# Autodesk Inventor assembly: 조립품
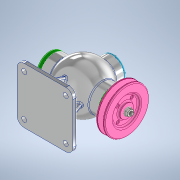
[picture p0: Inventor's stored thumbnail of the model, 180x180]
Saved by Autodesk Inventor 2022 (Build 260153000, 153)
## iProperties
Created: 2024-04
Part Number: 조립품
Document SubType Name: Assembly
Designer: Admin
Author: Admin
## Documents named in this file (16)
- C:\Users\Admin\Desktop\740406V1001\조립품.iam
- C:\Users\Admin\Desktop\740406V1001\본체.ipt
- C:\Users\Admin\Desktop\740406V1001\뒤커버.ipt
- C:\Users\Admin\Desktop\740406V1001\앞커버.ipt
- C:\Users\Admin\Desktop\740406V1001\베어링- 6202.ipt
- KS B 2023 - 6202 - 15 x 35 x 11 - 7.8.ipt
- C:\Users\Admin\Desktop\740406V1001\오일실 15 30 7.ipt
- C:\Users\Admin\Desktop\740406V1001\상부커버.ipt
- C:\Users\Admin\Desktop\740406V1001\칼라.ipt
- C:\Users\Admin\Desktop\740406V1001\편심축.ipt
- C:\Users\Admin\Desktop\740406V1001\키 4 x 4 x 12.ipt
- C:\Users\Admin\Desktop\740406V1001\V-벨트풀리.ipt
- C:\Users\Admin\Desktop\740406V1001\너트 M8.ipt
- C:\Users\Admin\Desktop\740406V1001\슬라이드.ipt
- C:\Users\Admin\Desktop\740406V1001\볼트 M4 x 16.ipt
- C:\Users\Admin\Desktop\740406V1001\볼트 M4 x 12.ipt
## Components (15 placed, 4 different names)
1. KS B 2023 - 6202 - 15 x 35 x 11 - 7.8:2
2. KS B 2023 - 6202 - 15 x 35 x 11 - 7.8:3
3. V-벨트풀리:1
4. ISO 4762 M4 x 16:1
5. ISO 4762 M4 x 16:2
6. ISO 4762 M4 x 16:3
7. ISO 4762 M4 x 16:4
8. ISO 4762 M4 x 16:5
9. ISO 4762 M4 x 16:6
10. ISO 4762 M4 x 16:7
11. ISO 4762 M4 x 16:8
12. KS B 1021 - 에 따름 ISO 1207 - 미터 A  M 4 x 12:1
13. KS B 1021 - 에 따름 ISO 1207 - 미터 A  M 4 x 12:2
14. KS B 1021 - 에 따름 ISO 1207 - 미터 A  M 4 x 12:3
15. KS B 1021 - 에 따름 ISO 1207 - 미터 A  M 4 x 12:4
